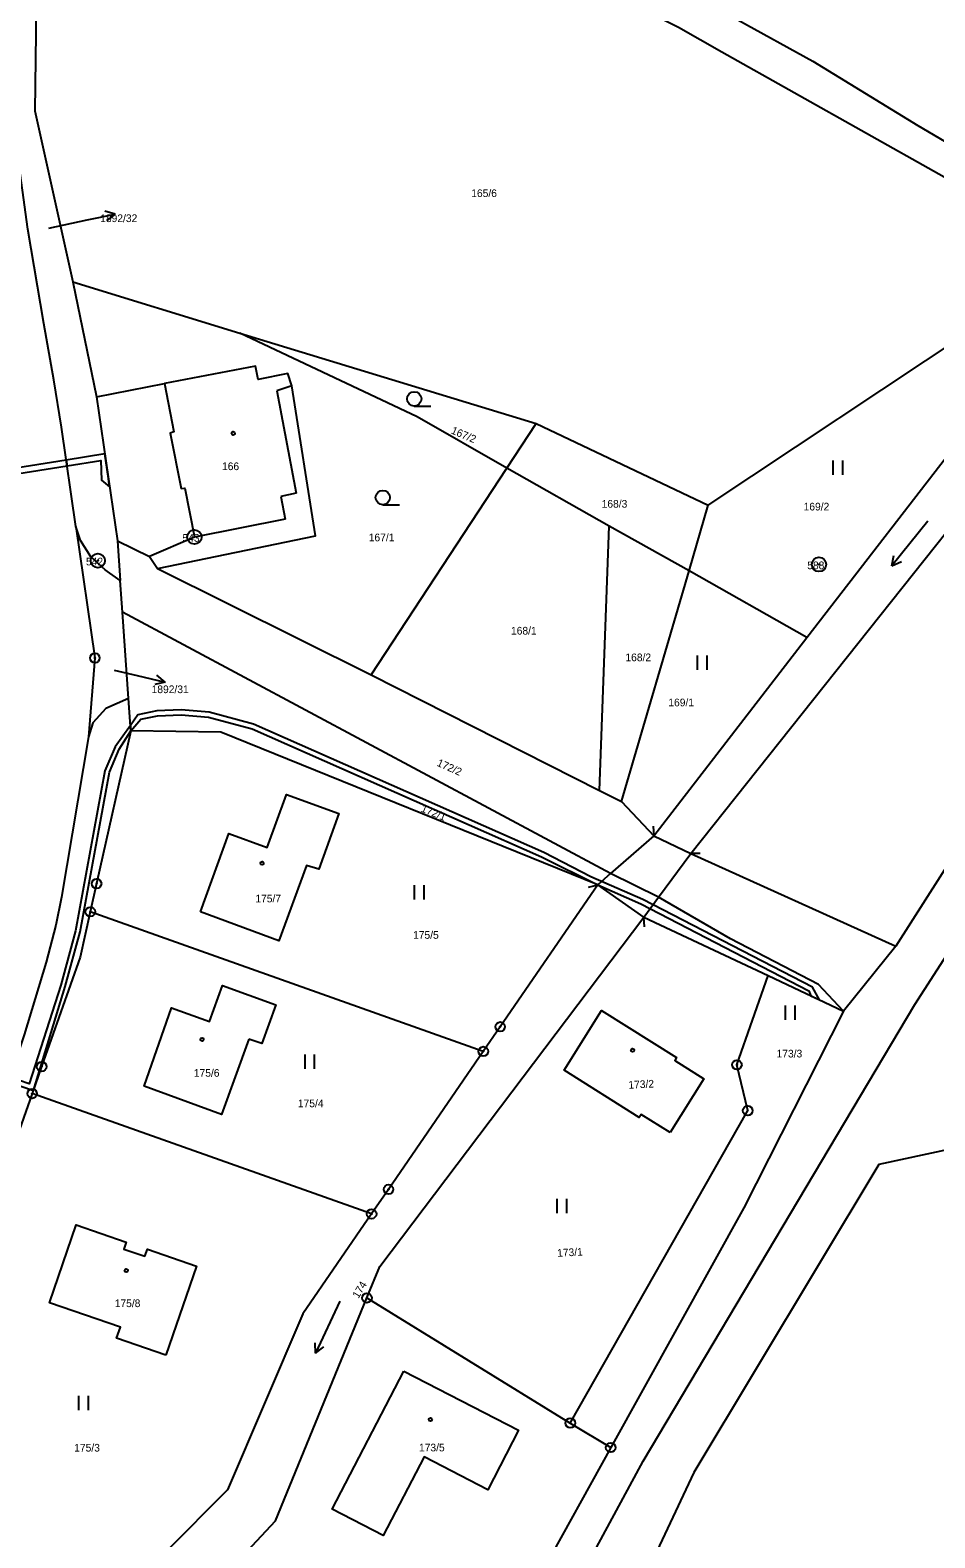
# Model space of a CAD drawing. Extents: x -587171 to -555306, y -1167727 to -1074732.
# Drawn here: x -559822.7 to -559728, y -1077125.8 to -1076968 of the extents above; entities that cross this region are included whole.
import ezdxf

# ---------------------------------------------------------------- set-up
doc = ezdxf.new("R2010")
doc.units = 0
for name, color, linetype in [('Hranice parcel', 7, 'Continuous'), ('Parcelní čísla', 7, 'Continuous'), ('Pop  PČ popisy', 7, 'Continuous'), ('Poz předměty', 7, 'Continuous'), ('Vnitřní kresba', 7, 'Continuous'), ('Věcná břemena k části', 7, 'Continuous'), ('Značky bodu BP', 7, 'Continuous'), ('Značky budov', 7, 'Continuous'), ('Značky kultur', 7, 'Continuous')]:
    doc.layers.add(name, color=color, linetype=linetype)

msp = doc.modelspace()

# ---------------------------------------------------------------- linework, layer by layer
at = {"layer": 'Hranice parcel'}
for p, q in [((-559751.72, -1077017.71), (-559712.43, -1076991.58)), ((-559741.39, -1077031.54), (-559711.14, -1076992.39)), ((-559818.24, -1076994.33), (-559800.74, -1076999.68)), ((-559753.56, -1077054.16), (-559706.55, -1076995.05)), ((-559800.74, -1076999.68), (-559769.74, -1077009.16)), ((-559693.29, -1077003.01), (-559732.09, -1077063.84)), ((-559772.81, -1077013.84), (-559769.74, -1077009.16)), ((-559769.74, -1077009.16), (-559751.72, -1077017.71)), ((-559787.01, -1077035.47), (-559772.81, -1077013.84)), ((-559762.08, -1077019.88), (-559772.81, -1077013.84)), ((-559753.73, -1077024.58), (-559751.72, -1077017.71)), ((-559763.12, -1077047.57), (-559762.08, -1077019.88)), ((-559753.73, -1077024.58), (-559762.08, -1077019.88)), ((-559813.57, -1077021.42), (-559810.22, -1077023.06)), ((-559813.57, -1077021.42), (-559813.27, -1077025.59)), ((-559810.22, -1077023.06), (-559809.39, -1077024.33)), ((-559809.39, -1077024.33), (-559787.01, -1077035.47)), ((-559813.04, -1077028.88), (-559813.27, -1077025.59)), ((-559760.82, -1077048.73), (-559753.73, -1077024.58)), ((-559741.39, -1077031.54), (-559753.73, -1077024.58)), ((-559812.41, -1077037.94), (-559813.04, -1077028.88)), ((-559757.43, -1077052.31), (-559741.39, -1077031.54)), ((-559787.01, -1077035.47), (-559763.12, -1077047.57)), ((-559812.17, -1077041.3), (-559812.41, -1077037.94)), ((-559763.12, -1077047.57), (-559760.82, -1077048.73)), ((-559760.82, -1077048.73), (-559757.43, -1077052.31)), ((-559757.43, -1077052.31), (-559753.56, -1077054.16)), ((-559753.56, -1077054.16), (-559732.09, -1077063.84)), ((-559758.48, -1077060.82), (-559763.29, -1077057.42)), ((-559775.27, -1077074.87), (-559816.41, -1077060.26)), ((-559758.48, -1077060.82), (-559745.46, -1077066.94)), ((-559732.09, -1077063.84), (-559737.55, -1077070.66)), ((-559748.72, -1077076.27), (-559745.46, -1077066.94)), ((-559745.46, -1077066.94), (-559737.55, -1077070.66)), ((-559786.96, -1077091.88), (-559822.49, -1077079.28)), ((-559787.45, -1077100.67), (-559766.16, -1077113.76)), ((-559766.16, -1077113.76), (-559761.93, -1077116.33)), ((-559761.93, -1077116.33), (-559776.08, -1077141.84))]:
    msp.add_line(p, q, dxfattribs=at)
for points in [[(-559819.52, -1076929.72), (-559789.34, -1076946.47), (-559756.49, -1076962.53), (-559740.76, -1076971.23), (-559729.78, -1076977.96), (-559713.09, -1076987.78), (-559709.61, -1076989.7)], [(-559712.43, -1076991.58), (-559750.31, -1076970.28), (-559754.85, -1076967.72), (-559790.36, -1076949.92), (-559820.03, -1076934.98)], [(-559817.92, -1077019.93), (-559819.43, -1077009.52), (-559820.21, -1077004.57), (-559821.27, -1076998.68), (-559822.96, -1076988.81), (-559824.18, -1076979.89), (-559824.89, -1076969.92), (-559824.93, -1076960.91), (-559824.5, -1076951.91), (-559823.69, -1076942.95)], [(-559821.95, -1076954.78), (-559822.2, -1076976.41), (-559818.24, -1076994.33)], [(-559818.24, -1076994.33), (-559815.76, -1077006.35), (-559813.57, -1077021.42)], [(-559772.81, -1077013.84), (-559782.2, -1077008.44), (-559800.74, -1076999.68)], [(-559809.39, -1077024.33), (-559792.82, -1077020.91), (-559795.32, -1077005.21), (-559795.73, -1077003.92), (-559798.84, -1077004.54), (-559799.11, -1077003.15), (-559808.65, -1077004.97), (-559807.66, -1077010.04), (-559808.04, -1077010.16), (-559806.9, -1077015.97), (-559806.51, -1077015.92), (-559805.51, -1077021.03), (-559810.22, -1077023.06)], [(-559817.92, -1077019.93), (-559815.93, -1077033.69), (-559816.6, -1077041.94)], [(-559813.27, -1077025.59), (-559814.85, -1077024.48), (-559816.36, -1077023.11), (-559817.45, -1077021.39), (-559817.92, -1077019.93)], [(-559737.55, -1077070.66), (-559740.18, -1077067.86), (-559749.38, -1077063.1), (-559756.94, -1077058.73), (-559761.95, -1077056.26), (-559813.04, -1077028.88)], [(-559812.41, -1077037.94), (-559814.79, -1077038.97), (-559816.13, -1077040.49), (-559816.6, -1077041.94)], [(-559812.17, -1077041.3), (-559815.75, -1077057.31), (-559816.41, -1077060.26)], [(-559763.29, -1077057.42), (-559802.73, -1077041.45), (-559812.17, -1077041.3)], [(-559816.6, -1077041.94), (-559819.41, -1077058.74), (-559820.03, -1077061.65), (-559821.04, -1077065.52), (-559823.32, -1077073.15), (-559826.24, -1077081.64), (-559828.56, -1077087.59), (-559836.17, -1077104.99), (-559841.38, -1077116.88), (-559843.69, -1077122.42), (-559846.42, -1077129.5), (-559846.09, -1077129.62), (-559844.82, -1077130.09), (-559843.82, -1077130.46)], [(-559804.89, -1077060.26), (-559801.92, -1077052.05), (-559797.9, -1077053.51), (-559795.86, -1077047.97), (-559790.38, -1077049.98), (-559792.5, -1077055.8), (-559793.76, -1077055.4), (-559796.67, -1077063.3), (-559804.89, -1077060.26)], [(-559763.29, -1077057.42), (-559773.5, -1077072.29), (-559775.27, -1077074.87)], [(-559816.41, -1077060.26), (-559817.47, -1077065.01), (-559821.5, -1077076.46), (-559822.49, -1077079.28)], [(-559787.45, -1077100.67), (-559786.1, -1077097.37), (-559758.48, -1077060.82)], [(-559799.8, -1077073.57), (-559802.67, -1077081.48), (-559810.77, -1077078.51), (-559807.92, -1077070.3), (-559803.93, -1077071.73), (-559802.58, -1077067.98), (-559797, -1077069.99), (-559798.46, -1077074.04), (-559799.8, -1077073.57)], [(-559755.71, -1077083.36), (-559758.76, -1077081.47), (-559758.96, -1077081.77), (-559766.81, -1077076.82), (-559762.9, -1077070.57), (-559755.06, -1077075.51), (-559755.22, -1077075.83), (-559752.18, -1077077.75), (-559755.71, -1077083.36)], [(-559737.55, -1077070.66), (-559748, -1077091.24), (-559761.93, -1077116.33)], [(-559775.27, -1077074.87), (-559785.19, -1077089.31), (-559786.96, -1077091.88)], [(-559766.16, -1077113.76), (-559747.59, -1077081.07), (-559748.72, -1077076.27)], [(-559822.49, -1077079.28), (-559825.6, -1077088.11), (-559834.22, -1077106.14), (-559841.22, -1077123.3)], [(-559716.92, -1077078.99), (-559718.8, -1077083.46), (-559733.87, -1077086.69), (-559753.22, -1077118.95), (-559762.33, -1077138.31), (-559766.54, -1077149.07), (-559769.65, -1077152.21)], [(-559786.96, -1077091.88), (-559794.15, -1077102.35), (-559802.04, -1077120.75), (-559808.49, -1077127.23), (-559816.84, -1077129.72), (-559838.86, -1077123.92), (-559841.22, -1077123.3)], [(-559808.51, -1077106.66), (-559813.67, -1077104.87), (-559813.25, -1077103.74), (-559820.69, -1077101.17), (-559817.88, -1077093.01), (-559812.64, -1077094.82), (-559812.89, -1077095.55), (-559810.69, -1077096.31), (-559810.42, -1077095.58), (-559805.29, -1077097.35), (-559808.51, -1077106.66)], [(-559815.3, -1077135.92), (-559806.38, -1077134), (-559797.01, -1077123.99), (-559787.45, -1077100.67)], [(-559783.58, -1077108.34), (-559771.59, -1077114.52), (-559774.81, -1077120.76), (-559781.47, -1077117.31), (-559785.75, -1077125.53), (-559791.08, -1077122.77), (-559783.58, -1077108.34)]]:
    msp.add_lwpolyline(points, dxfattribs=at)
at = {"layer": 'Pop  PČ popisy'}
for p, q in [((-559820.76, -1076988.72), (-559816.75, -1076987.85)), ((-559816.75, -1076987.85), (-559813.82, -1076987.23)), ((-559813.82, -1076987.23), (-559814.9, -1076986.94)), ((-559813.82, -1076987.23), (-559814.69, -1076987.92)), ((-559813.92, -1077034.96), (-559811.5, -1077035.54)), ((-559808.58, -1077036.22), (-559809.44, -1077035.5)), ((-559811.5, -1077035.54), (-559808.58, -1077036.22)), ((-559808.58, -1077036.22), (-559809.66, -1077036.48))]:
    msp.add_line(p, q, dxfattribs=at)
at = {"layer": 'Poz předměty'}
for p, q in [((-559730.08, -1077069.96), (-559688.97, -1077005.86)), ((-559758.55, -1077117.74), (-559730.08, -1077069.96)), ((-559773.19, -1077144.82), (-559758.55, -1077117.74))]:
    msp.add_line(p, q, dxfattribs=at)
at = {"layer": 'Vnitřní kresba'}
for p, q in [((-559815.76, -1077006.35), (-559808.65, -1077004.97)), ((-559795.32, -1077005.21), (-559796.89, -1077005.72)), ((-559796.89, -1077005.72), (-559794.87, -1077016.44)), ((-559794.87, -1077016.44), (-559796.46, -1077016.78)), ((-559796.46, -1077016.78), (-559796, -1077019.18)), ((-559796, -1077019.18), (-559805.51, -1077021.03)), ((-559757.43, -1077052.31), (-559761.95, -1077056.26)), ((-559757.48, -1077051.31), (-559757.43, -1077052.31)), ((-559756.94, -1077058.73), (-559753.56, -1077054.16)), ((-559752.56, -1077054.14), (-559753.56, -1077054.16)), ((-559764.26, -1077057.68), (-559763.29, -1077057.42)), ((-559761.95, -1077056.26), (-559763.29, -1077057.42)), ((-559758.48, -1077060.82), (-559756.94, -1077058.73)), ((-559758.41, -1077061.82), (-559758.48, -1077060.82))]:
    msp.add_line(p, q, dxfattribs=at)
at = {"layer": 'Věcná břemena k části'}
for points in [[(-559824.85, -1077013.93), (-559824.76, -1077014.52), (-559818.84, -1077013.58), (-559818.93, -1077012.98)], [(-559814.39, -1077015.77), (-559814.52, -1077014.89), (-559814.89, -1077012.34), (-559818.93, -1077012.98), (-559818.84, -1077013.58), (-559815.32, -1077013.02), (-559815.22, -1077015.09)], [(-559740.99, -1077069.04), (-559740.07, -1077069.47), (-559740.8, -1077068.16), (-559758.57, -1077058.98), (-559764.03, -1077056.58), (-559768.94, -1077054.06), (-559799.32, -1077040.62), (-559803.96, -1077039.37), (-559806.89, -1077039.13), (-559809.44, -1077039.24), (-559811.42, -1077039.64), (-559812.21, -1077040.75), (-559812.17, -1077041.3), (-559811.12, -1077040.1), (-559809.38, -1077039.74), (-559806.89, -1077039.63), (-559804.04, -1077039.87), (-559799.48, -1077041.1), (-559769.16, -1077054.51), (-559763.29, -1077057.42), (-559758.79, -1077059.44), (-559741.2, -1077068.52)], [(-559824.83, -1077077.55), (-559825, -1077078.05), (-559822.37, -1077078.95), (-559819.03, -1077068.08), (-559817.48, -1077062.36), (-559814.41, -1077045.65), (-559813.38, -1077043.22), (-559812.17, -1077041.3), (-559812.21, -1077040.75), (-559813.82, -1077042.98), (-559814.89, -1077045.51), (-559817.96, -1077062.24), (-559819.51, -1077067.94), (-559822.81, -1077078.27)]]:
    msp.add_lwpolyline(points, close=True, dxfattribs=at)
at = {"layer": 'Značky bodu BP'}
for centre, radius in [((-559805.51, -1077021.03), 0.75), ((-559805.51, -1077021.03), 0.03), ((-559815.62, -1077023.5), 0.75), ((-559815.62, -1077023.5), 0.03), ((-559740.13, -1077023.9), 0.75), ((-559740.13, -1077023.9), 0.03), ((-559815.93, -1077033.69), 0.5), ((-559815.93, -1077033.69), 0.0303), ((-559815.75, -1077057.31), 0.5), ((-559815.75, -1077057.31), 0.0303), ((-559816.41, -1077060.26), 0.5), ((-559816.41, -1077060.26), 0.0303), ((-559773.5, -1077072.29), 0.5), ((-559773.5, -1077072.29), 0.0303), ((-559775.27, -1077074.87), 0.5), ((-559775.27, -1077074.87), 0.0303), ((-559821.5, -1077076.46), 0.5), ((-559821.5, -1077076.46), 0.0303), ((-559748.72, -1077076.27), 0.5), ((-559748.72, -1077076.27), 0.0303), ((-559822.49, -1077079.28), 0.5), ((-559822.49, -1077079.28), 0.0303), ((-559747.59, -1077081.07), 0.5), ((-559747.59, -1077081.07), 0.0303), ((-559785.19, -1077089.31), 0.5), ((-559785.19, -1077089.31), 0.0303), ((-559786.96, -1077091.88), 0.5), ((-559786.96, -1077091.88), 0.0303), ((-559787.45, -1077100.67), 0.5), ((-559787.45, -1077100.67), 0.0303), ((-559766.16, -1077113.76), 0.5), ((-559766.16, -1077113.76), 0.0303), ((-559761.93, -1077116.33), 0.5), ((-559761.93, -1077116.33), 0.0303)]:
    msp.add_circle(centre, radius, dxfattribs=at)
at = {"layer": 'Značky budov'}
for centre in [(-559801.45, -1077010.18), (-559798.42, -1077055.17), (-559804.71, -1077073.61), (-559759.64, -1077074.75), (-559812.65, -1077097.81), (-559780.8, -1077113.4)]:
    msp.add_circle(centre, 0.175, dxfattribs=at)
at = {"layer": 'Značky kultur'}
for p, q in [((-559782.5, -1077007.32), (-559780.75, -1077007.32)), ((-559738.65, -1077014.54), (-559738.65, -1077013.04)), ((-559737.65, -1077014.54), (-559737.65, -1077013.04)), ((-559785.79, -1077017.65), (-559784.04, -1077017.65)), ((-559728.73, -1077019.38), (-559732.51, -1077024.04)), ((-559732.51, -1077024.04), (-559732.28, -1077022.96)), ((-559732.51, -1077024.04), (-559731.5, -1077023.6)), ((-559752.85, -1077034.94), (-559752.85, -1077033.44)), ((-559751.85, -1077034.94), (-559751.85, -1077033.44)), ((-559782.46, -1077058.98), (-559782.46, -1077057.48)), ((-559781.46, -1077058.98), (-559781.46, -1077057.48)), ((-559743.64, -1077071.57), (-559743.64, -1077070.07)), ((-559742.64, -1077071.57), (-559742.64, -1077070.07)), ((-559793.93, -1077076.68), (-559793.93, -1077075.18)), ((-559792.93, -1077076.68), (-559792.93, -1077075.18)), ((-559767.53, -1077091.8), (-559767.53, -1077090.3)), ((-559766.53, -1077091.8), (-559766.53, -1077090.3)), ((-559790.29, -1077101.02), (-559792.82, -1077106.46)), ((-559792.82, -1077106.46), (-559792.86, -1077105.36)), ((-559792.82, -1077106.46), (-559791.95, -1077105.79)), ((-559817.61, -1077112.4), (-559817.61, -1077110.9)), ((-559816.61, -1077112.4), (-559816.61, -1077110.9))]:
    msp.add_line(p, q, dxfattribs=at)
for centre in [(-559782.5, -1077006.57), (-559785.79, -1077016.9)]:
    msp.add_circle(centre, 0.75, dxfattribs=at)

# ---------------------------------------------------------------- texts
at = {"layer": 'Parcelní čísla'}
for s, p in [('165/6', (-559776.53, -1076985.45)), ('1892/32', (-559815.37, -1076988.07)), ('166', (-559802.62, -1077014.03)), ('168/3', (-559762.88, -1077017.96)), ('169/2', (-559741.74, -1077018.25)), ('167/1', (-559787.26, -1077021.48)), ('168/1', (-559772.37, -1077031.24)), ('168/2', (-559760.39, -1077034.03)), ('1892/31', (-559809.99, -1077037.37)), ('169/1', (-559755.9, -1077038.75)), ('175/7', (-559799.13, -1077059.27)), ('175/5', (-559782.62, -1077063.08)), ('173/3', (-559744.57, -1077075.5)), ('175/6', (-559805.57, -1077077.52)), ('175/4', (-559794.68, -1077080.71)), ('175/8', (-559813.85, -1077101.63)), ('175/3', (-559818.09, -1077116.75)), ('173/5', (-559782, -1077116.73))]:
    msp.add_text(s, height=0.803, dxfattribs=at).set_placement(p)
for s, rotation, p in [('167/2', 337, (-559778.71, -1077010.17)), ('172/2', 336, (-559780.2, -1077044.95)), ('172/1', 338, (-559781.86, -1077049.75)), ('173/2', 3, (-559760.06, -1077078.78)), ('173/1', 3, (-559767.52, -1077096.37)), ('174', 59, (-559788.34, -1077100.78))]:
    msp.add_text(s, height=0.803, rotation=rotation, dxfattribs=at).set_placement(p)
at = {"layer": 'Značky bodu BP'}
for s, p in [('543', (-559806.76, -1077021.53)), ('542', (-559816.86, -1077024)), ('588', (-559741.36, -1077024.4))]:
    msp.add_text(s, height=0.803, dxfattribs=at).set_placement(p)

doc.saveas('drawing.dxf')
